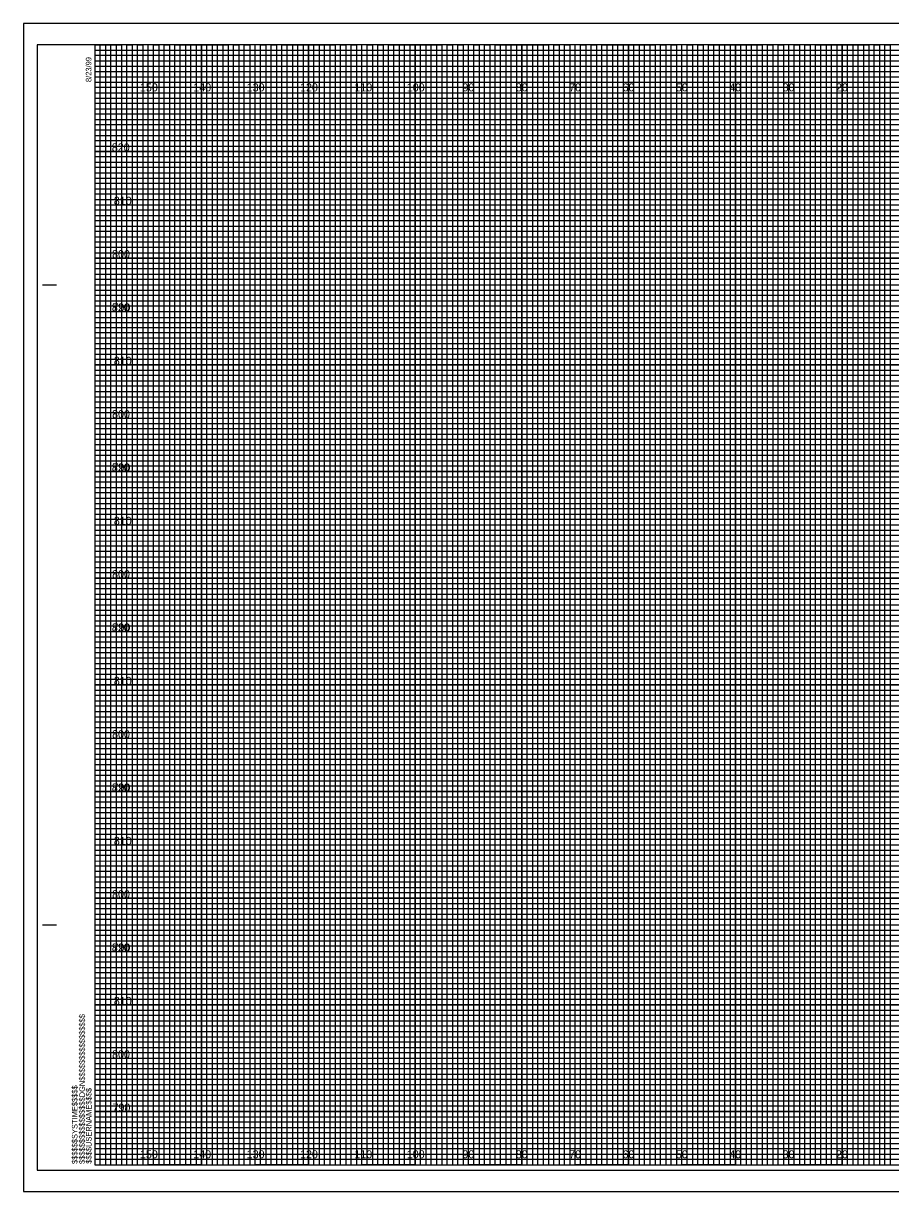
# Model space of a CAD drawing. Extents: x -13 to 323, y 875 to 1094.
# Drawn here: x -13.4 to 149.1, y 875 to 1094 of the extents above; entities that cross this region are included whole.
import ezdxf

# ---------------------------------------------------------------- set-up
doc = ezdxf.new("R2010")
doc.units = 0
for name, color, linetype in [('Exist Cross Section Cell', 7, 'Continuous'), ('Exist XS Ground Line', 7, 'Continuous'), ('Prop XS Dump Level', 7, 'Continuous'), ('Prop XS EOT Tick Mark', 7, 'Continuous'), ('Prop XS Finish Grade', 7, 'Continuous'), ('Prop XS Finish Grade Paved Shoulder', 7, 'Continuous'), ('Prop XS Pvmt Edge Slope', 7, 'Continuous'), ('Prop XS SE Text', 7, 'Continuous'), ('Prop XS Side Slope Text', 7, 'Continuous'), ('Prop XS SS Elevation Text', 7, 'Continuous'), ('Prop XS Subgrade Earthwork', 7, 'Continuous')]:
    doc.layers.add(name, color=color, linetype=linetype)

msp = doc.modelspace()

# ---------------------------------------------------------------- linework, layer by layer
at = {"layer": 'Exist XS Ground Line'}
for p, q in [((10, 1090), (0, 1090)), ((10, 880), (10, 1090)), ((30, 1090), (20, 1090)), ((20, 1090), (20, 880)), ((30, 880), (30, 1090)), ((50, 1090), (40, 1090)), ((40, 1090), (40, 880)), ((50, 880), (50, 1090)), ((70, 1090), (60, 1090)), ((60, 1090), (60, 880)), ((70, 880), (70, 1090)), ((90, 1090), (80, 1090)), ((80, 1090), (80, 880)), ((90, 880), (90, 1090)), ((110, 1090), (100, 1090)), ((100, 1090), (100, 880)), ((110, 880), (110, 1090)), ((130, 1090), (120, 1090)), ((120, 1090), (120, 880)), ((130, 880), (130, 1090)), ((150, 1090), (140, 1090)), ((140, 1090), (140, 880)), ((20, 880), (10, 880)), ((40, 880), (30, 880)), ((60, 880), (50, 880)), ((80, 880), (70, 880)), ((100, 880), (90, 880)), ((120, 880), (110, 880)), ((140, 880), (130, 880))]:
    msp.add_line(p, q, dxfattribs=at)
for points in [[(0, 1080), (320, 1080), (320, 1070), (0, 1070)], [(0, 1060), (320, 1060), (320, 1050), (0, 1050)], [(0, 1040), (320, 1040), (320, 1030), (0, 1030)], [(0, 1020), (320, 1020), (320, 1010), (0, 1010)], [(0, 1000), (320, 1000), (320, 990), (0, 990)], [(0, 980), (320, 980), (320, 970), (0, 970)], [(0, 960), (320, 960), (320, 950), (0, 950)], [(0, 940), (320, 940), (320, 930), (0, 930)], [(0, 920), (320, 920), (320, 910), (0, 910)], [(0, 900), (320, 900), (320, 890), (0, 890)]]:
    msp.add_lwpolyline(points, dxfattribs=at)
at = {"layer": 'Prop XS Dump Level'}
for points in [[(0, 1090), (5, 1090), (5, 880), (15, 880), (15, 1090), (25, 1090), (25, 880), (35, 880), (35, 1090), (45, 1090), (45, 880), (55, 880), (55, 1090), (65, 1090), (65, 880), (75, 880), (75, 1090), (85, 1090), (85, 880), (95, 880), (95, 1090), (105, 1090), (105, 880), (115, 880), (115, 1090), (125, 1090), (125, 880), (135, 880), (135, 1090), (145, 1090), (145, 880), (155, 880)], [(0, 1085), (275, 1085)], [(0, 1065), (320, 1065), (320, 1075), (0, 1075)], [(0, 1045), (320, 1045), (320, 1055), (0, 1055)], [(0, 1025), (320, 1025), (320, 1035), (0, 1035)], [(0, 1005), (320, 1005), (320, 1015), (0, 1015)], [(0, 985), (320, 985), (320, 995), (0, 995)], [(0, 965), (320, 965), (320, 975), (0, 975)], [(0, 945), (320, 945), (320, 955), (0, 955)], [(0, 925), (320, 925), (320, 935), (0, 935)], [(0, 905), (320, 905), (320, 915), (0, 915)], [(0, 885), (320, 885), (320, 895), (0, 895)]]:
    msp.add_lwpolyline(points, dxfattribs=at)
at = {"layer": 'Prop XS Finish Grade'}
msp.add_lwpolyline([(-10.8, 879), (322.4, 879), (322.4, 1090), (-10.8, 1090)], close=True, dxfattribs=at)
at = {"layer": 'Prop XS Finish Grade Paved Shoulder'}
for p, q in [((10, 880), (10, 1090)), ((20, 880), (20, 1090)), ((30, 880), (30, 1090)), ((40, 880), (40, 1090)), ((50, 880), (50, 1090)), ((60, 880), (60, 1090)), ((70, 880), (70, 1090)), ((80, 880), (80, 1090)), ((90, 880), (90, 1090)), ((100, 880), (100, 1090)), ((110, 880), (110, 1090)), ((120, 880), (120, 1090)), ((130, 880), (130, 1090)), ((140, 880), (140, 1090)), ((0, 1080), (320, 1080)), ((0, 1070), (320, 1070)), ((0, 1060), (320, 1060)), ((0, 1050), (320, 1050)), ((0, 1040), (320, 1040)), ((0, 1030), (320, 1030)), ((0, 1020), (320, 1020)), ((0, 1010), (320, 1010)), ((0, 1000), (320, 1000)), ((0, 990), (320, 990)), ((0, 980), (320, 980)), ((0, 970), (320, 970)), ((0, 960), (320, 960)), ((0, 950), (320, 950)), ((0, 940), (320, 940)), ((0, 930), (320, 930)), ((0, 920), (320, 920)), ((0, 910), (320, 910)), ((0, 900), (320, 900)), ((0, 890), (320, 890))]:
    msp.add_line(p, q, dxfattribs=at)
at = {"layer": 'Prop XS Pvmt Edge Slope'}
for p, q in [((323.3, 1094), (-13.4, 1094)), ((-13.4, 1094), (-13.4, 875)), ((-13.4, 875), (323.3, 875))]:
    msp.add_line(p, q, dxfattribs=at)
at = {"layer": 'Prop XS SE Text'}
for p, q in [((0, 1089), (260, 1089)), ((260, 1087.98), (0, 1087.98)), ((0, 1087.98), (0, 1087)), ((0, 1087), (260, 1087)), ((260, 1085.89), (0, 1085.89)), ((0, 1085.89), (0, 1084)), ((0, 1084), (320, 1084))]:
    msp.add_line(p, q, dxfattribs=at)
for points in [[(0, 1083), (270, 1083), (320, 1083), (320, 1082), (0, 1082)], [(0, 1081), (320, 1081), (320, 1079), (0, 1079)], [(0, 1078), (320, 1078), (320, 1077), (0, 1076.98)], [(0, 1076), (320, 1076), (320, 1074), (0, 1074)], [(0, 1073), (320, 1073), (320, 1072), (0, 1072)], [(0, 1071), (320, 1071), (320, 1069), (0, 1069)], [(0, 1068), (320, 1068), (320, 1067), (0, 1067)], [(0, 1066), (320, 1066), (320, 1064), (0, 1064)], [(0, 1063), (320, 1063), (320, 1062), (0, 1062)], [(0, 1061), (320, 1061), (320, 1059), (0, 1059)], [(0, 1058), (320, 1058), (320, 1057), (0, 1057)], [(0, 1056), (320, 1056), (320, 1053.95), (320, 1053), (320, 1052), (0, 1052)], [(0, 1054), (320, 1054), (320, 1053), (0, 1053)], [(0, 1051), (320, 1051), (320, 1049), (0, 1049.03)], [(0, 1049.03), (320, 1049), (320, 1048), (0, 1048)], [(0, 1047), (320, 1047), (320, 1046), (0, 1046)], [(0, 1044), (320, 1044), (320, 1043), (0, 1043)], [(0, 1042), (320, 1042), (320, 1041), (0, 1041)], [(-0.07, 1038.89), (320, 1038.89), (320, 1037.88), (-0.07, 1037.88)], [(0, 1037), (320, 1037), (320, 1036), (0, 1036)], [(0, 1034), (320, 1034), (320, 1033), (0, 1033)], [(0, 1032), (320, 1032), (320, 1031), (0, 1031)], [(0, 1029), (320, 1029), (320, 1028), (0, 1028)], [(0, 1027), (320, 1027), (320, 1026), (0, 1026)], [(0, 1024), (320, 1024), (320, 1023), (0, 1023)], [(0, 1022), (320, 1022), (320, 1021), (0, 1021)], [(0, 1019), (320, 1019), (319.99, 1017.98), (0, 1018)], [(0, 1017), (320, 1017), (320, 1016), (0, 1016)], [(0, 1014), (320, 1014), (320, 1013), (0, 1013)], [(0, 1012), (320, 1012), (320, 1011), (0, 1011)], [(0, 1009), (320, 1009), (320, 1008), (0, 1008)], [(0, 1007), (320, 1007), (320, 1006), (0, 1006)], [(0, 1004), (320, 1004), (320, 1003), (0, 1003)], [(0, 1002), (320, 1002), (320, 1001), (0, 1001)], [(0, 999), (320, 999), (320, 998), (0, 998)], [(0, 996.99), (320.07, 996.91), (320, 996), (0, 996)], [(0, 994), (320, 994), (320, 993), (0, 993)], [(0, 992), (320, 992), (320, 991), (0, 991)], [(0, 989), (320, 989), (320, 988), (0, 988)], [(0, 987), (320, 987), (320, 986), (0, 986)], [(0, 984), (320, 984), (320, 983), (0, 983)], [(0, 982), (320, 982), (320, 981), (0, 981)], [(0, 979), (320, 979), (320, 978), (0, 978)], [(0, 977), (320, 977), (320, 976), (0, 976)], [(0, 974), (320, 974), (320, 973), (0, 973)], [(0, 972), (320, 972), (320, 971), (0, 971)], [(0, 969), (320, 969), (320, 968), (0, 968)], [(0, 967), (320, 967), (320, 966), (0, 966)], [(0, 964), (320, 964), (320, 963), (0, 963)], [(0, 962), (320, 962), (320, 961), (0, 961)], [(0, 959), (320, 959), (319.99, 957.98), (0, 958)], [(0, 957), (320, 957), (320, 956), (0, 956)], [(0, 954), (320, 954), (320, 953), (0, 953)], [(0, 952), (320, 952), (320, 951), (0, 951)], [(0, 949), (320, 949), (320, 948), (0, 948)], [(0, 947), (320, 947), (320, 946), (0, 946)], [(0, 944), (320, 944), (320, 943), (0, 943)], [(0, 942), (320, 942), (320, 941), (0, 941)], [(0, 939), (320, 939), (320, 938), (0, 938)], [(0, 936.99), (320.07, 936.91), (320, 936), (0, 936)], [(0, 934), (320, 934), (320, 933), (0, 933)], [(0, 932), (320, 932), (320, 931), (0, 931)], [(0, 929), (320, 929), (320, 928), (0, 928)], [(0, 927), (320, 927), (320, 926), (0, 926)], [(0, 924), (320, 924), (320, 923), (0, 923)], [(0, 922), (320, 922), (320, 921), (0, 921)], [(0, 919), (320, 919), (320, 918), (0, 918)], [(0, 917), (320, 917), (320, 916), (0, 916)], [(0, 914), (320, 914), (320, 913), (0, 913)], [(0, 912), (320, 912), (320, 911), (0, 911)], [(0, 909), (320, 909), (320, 908), (0, 908)], [(0, 907), (320, 907), (320, 906), (0, 906)], [(0, 904), (320, 904), (320, 903), (0, 903)], [(0, 902), (320, 902), (320, 901), (0, 901)], [(0, 899), (320, 899), (320, 898), (0, 898)], [(0, 897), (320, 897), (320, 896), (0, 896)], [(0, 894), (320, 894), (320, 893), (0, 893)], [(0, 892), (320, 892), (320, 891), (0, 891)], [(0, 889), (320, 889), (320, 888), (0, 888)], [(0, 887), (320, 887), (320, 886), (0, 886)], [(0, 884), (320, 884), (320, 883), (0, 883)], [(0, 882), (320, 882), (320, 881), (0, 881)]]:
    msp.add_lwpolyline(points, dxfattribs=at)
at = {"layer": 'Prop XS Side Slope Text'}
for p, q in [((-9.8, 1045), (-7.3, 1045)), ((-9.7, 1045), (-7.2, 1045)), ((-9.8, 925), (-7.3, 925)), ((-9.7, 925), (-7.2, 925)), ((0, 880), (0, 880)), ((0, 880), (0, 880)), ((0, 880), (0, 880)), ((0, 880), (0, 880)), ((0, 880), (0, 880)), ((0, 880), (0, 880)), ((0, 880), (0, 880))]:
    msp.add_line(p, q, dxfattribs=at)
msp.add_lwpolyline([(320, 1090), (0, 1090), (0, 880), (320, 880)], close=True, dxfattribs=at)
at = {"layer": 'Prop XS SS Elevation Text'}
for points in [[(0, 880), (1, 880), (1, 1090), (2, 1090), (2, 880)], [(2, 880), (3, 880), (3, 1090), (4, 1090), (4, 880)], [(5, 880), (6, 880), (6, 1090), (7, 1090), (7, 880)], [(7, 880), (8, 880), (8, 1090), (9, 1090), (9, 880)], [(10, 880), (11, 880), (11, 1090), (12, 1090), (12, 880)], [(12, 880), (13, 880), (13, 1090), (14, 1090), (14, 880)], [(15, 880), (16, 880), (16, 1090), (17, 1090), (17, 880)], [(17, 880), (18, 880), (18, 1090), (19, 1090), (19, 880)], [(20, 880), (21, 880), (21, 1090), (22, 1090), (22, 880)], [(22, 880), (23, 880), (23, 1090), (24, 1090), (24, 880)], [(25, 880), (26, 880), (26, 1090), (27, 1090), (27, 880)], [(27, 880), (28, 880), (28, 1090), (29, 1090), (29, 880)], [(30, 880), (31, 880), (31, 1090), (32, 1090), (32, 880)], [(32, 880), (33, 880), (33, 1090), (34, 1090), (34, 880)], [(35, 880), (36, 880), (36, 1090), (37, 1090), (37, 880)], [(37, 880), (38, 880), (38, 1090), (39, 1090), (39, 880)], [(40, 880), (41, 880), (41, 1090), (42, 1090), (42, 880)], [(42, 880), (43, 880), (43, 1090), (44, 1090), (44, 880)], [(45, 880), (46, 880), (46, 1090), (47, 1090), (47, 880)], [(47, 880), (48, 880), (48, 1090), (49, 1090), (49, 880)], [(50, 880), (51, 880), (51, 1090), (52, 1090), (52, 880)], [(52, 880), (53, 880), (53, 1090), (54, 1090), (54, 880)], [(55, 880), (56, 880), (56, 1090), (57, 1090), (57, 880)], [(57, 880), (58, 880), (58, 1090), (59, 1090), (59, 880)], [(60, 880), (61, 880), (61, 1090), (62, 1090), (62, 880)], [(62, 880), (63, 880), (63, 1090), (64, 1090), (64, 880)], [(65, 880), (66, 880), (66, 1090), (67, 1090), (67, 880)], [(67, 880), (68, 880), (68, 1090), (69, 1090), (69, 880)], [(70, 880), (71, 880), (71, 1090), (72, 1090), (72, 880)], [(72, 880), (73, 880), (73, 1090), (74, 1090), (74, 880)], [(75, 880), (76, 880), (76, 1090), (77, 1090), (77, 880)], [(77, 880), (78, 880), (78, 1090), (79, 1090), (79, 880)], [(80, 880), (81, 880), (81, 1090), (82, 1090), (82, 880)], [(82, 880), (83, 880), (83, 1090), (84, 1090), (84, 880)], [(85, 880), (86, 880), (86, 1090), (87, 1090), (87, 880)], [(87, 880), (88, 880), (88, 1090), (89, 1090), (89, 880)], [(90, 880), (91, 880), (91, 1090), (92, 1090), (92, 880)], [(92, 880), (93, 880), (93, 1090), (94, 1090), (94, 880)], [(95, 880), (96, 880), (96, 1090), (97, 1090), (97, 880)], [(97, 880), (98, 880), (98, 1090), (99, 1090), (99, 880)], [(100, 880), (101, 880), (101, 1090), (102, 1090), (102, 880)], [(102, 880), (103, 880), (103, 1090), (104, 1090), (104, 880)], [(105, 880), (106, 880), (106, 1090), (107, 1090), (107, 880)], [(107, 880), (108, 880), (108, 1090), (109, 1090), (109, 880)], [(110, 880), (111, 880), (111, 1090), (112, 1090), (112, 880)], [(112, 880), (113, 880), (113, 1090), (114, 1090), (114, 880)], [(115, 880), (116, 880), (116, 1090), (117, 1090), (117, 880)], [(117, 880), (118, 880), (118, 1090), (119, 1090), (119, 880)], [(120, 880), (121, 880), (121, 1090), (122, 1090), (122, 880)], [(122, 880), (123, 880), (123, 1090), (124, 1090), (124, 880)], [(125, 880), (126, 880), (126, 1090), (127, 1090), (127, 880)], [(127, 880), (128, 880), (128, 1090), (129, 1090), (129, 880)], [(130, 880), (131, 880), (131, 1090), (132, 1090), (132, 880)], [(132, 880), (133, 880), (133, 1090), (134, 1090), (134, 880)], [(135, 880), (136, 880), (136, 1090), (137, 1090), (137, 880)], [(137, 880), (138, 880), (138, 1090), (139, 1090), (139, 880)], [(140, 880), (141, 880), (141, 1090), (142, 1090), (142, 880)], [(142, 880), (143, 880), (143, 1090), (144, 1090), (144, 880)], [(145, 880), (146, 880), (146, 1090), (147, 1090), (147, 880)], [(147, 880), (148, 880), (148, 1090), (149, 1090), (149, 880)]]:
    msp.add_lwpolyline(points, dxfattribs=at)
at = {"layer": 'Prop XS Subgrade Earthwork'}
msp.add_lwpolyline([(-13.4, 875), (323.3, 875), (323.3, 1094), (-13.4, 1094)], close=True, dxfattribs=at)

# ---------------------------------------------------------------- texts
at = {"layer": 'Exist Cross Section Cell'}
for s, p in [('150', (8.44, 1081.25)), ('140', (18.44, 1081.25)), ('130', (28.44, 1081.25)), ('120', (38.44, 1081.25)), ('110', (48.62, 1081.25)), ('100', (58.44, 1081.25)), ('90', (68.86, 1081.25)), ('80', (78.86, 1081.25)), ('70', (88.86, 1081.25)), ('60', (98.86, 1081.25)), ('50', (108.86, 1081.25)), ('40', (118.86, 1081.25)), ('30', (128.86, 1081.25)), ('20', (138.86, 1081.25)), ('150', (8.44, 881.25)), ('140', (18.44, 881.25)), ('130', (28.44, 881.25)), ('120', (38.44, 881.25)), ('110', (48.62, 881.25)), ('100', (58.44, 881.25)), ('90', (68.86, 881.25)), ('80', (78.86, 881.25)), ('70', (88.86, 881.25)), ('60', (98.86, 881.25)), ('50', (108.86, 881.25)), ('40', (118.86, 881.25)), ('30', (128.86, 881.25)), ('20', (138.86, 881.25))]:
    msp.add_text(s, height=1.5, dxfattribs=at).set_placement(p)
at = {"layer": 'Prop XS EOT Tick Mark'}
for s, p in [('820', (3.17, 1070)), ('810', (3.55, 1060)), ('800', (3.22, 1050)), ('820', (3.17, 1040)), ('790', (3.3, 1040)), ('810', (3.55, 1030)), ('800', (3.22, 1020)), ('820', (3.17, 1010)), ('790', (3.3, 1010)), ('810', (3.55, 1000)), ('800', (3.22, 990)), ('820', (3.17, 980)), ('790', (3.3, 980)), ('810', (3.55, 970)), ('800', (3.22, 960)), ('820', (3.17, 950)), ('790', (3.3, 950)), ('810', (3.55, 940)), ('800', (3.22, 930)), ('820', (3.17, 920)), ('790', (3.3, 920)), ('810', (3.55, 910)), ('800', (3.22, 900)), ('790', (3.3, 890))]:
    msp.add_text(s, height=1.5, dxfattribs=at).set_placement(p)
at = {"layer": 'Prop XS Side Slope Text'}
for s, p in [('8/23/99', (-0.65, 1083)), ('$$$$$$$$$$$$$$$$DGN$$$$$$$$$$$$$$$$', (-1.88, 880.18)), ('$$$$$$SYSTIME$$$$$', (-3.26, 880.18)), ('$$$$USERNAME$$$$', (-0.62, 880.23))]:
    msp.add_text(s, height=1.05, rotation=90, dxfattribs=at).set_placement(p)

doc.saveas('drawing.dxf')
